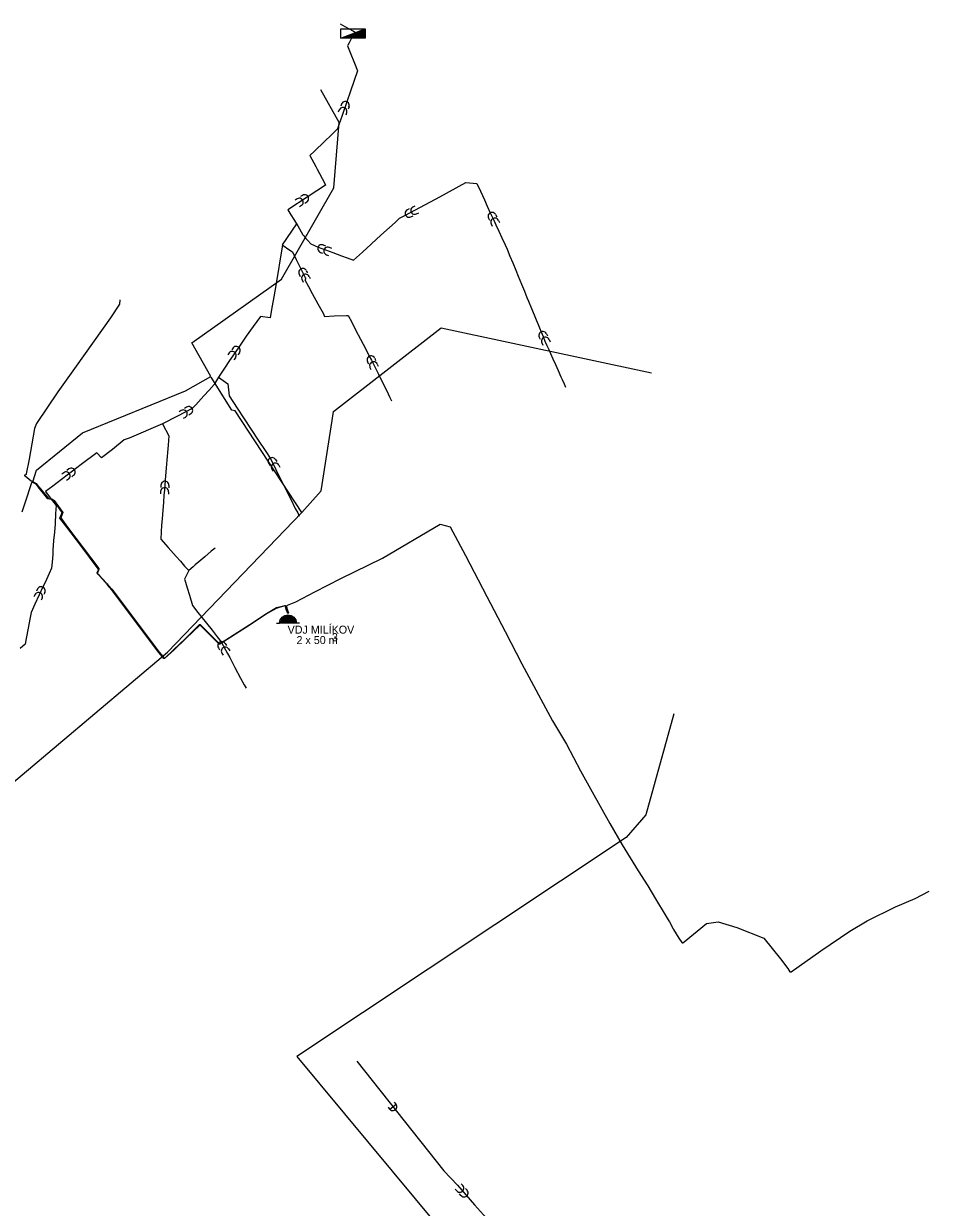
# Model space of a CAD drawing. Extents: x -445050 to -435119, y -1145927 to -1129778.
# Drawn here: x -442201 to -441070, y -1131257 to -1129778 of the extents above; entities that cross this region are included whole.
import ezdxf

# ---------------------------------------------------------------- set-up
doc = ezdxf.new("R2010")
doc.units = 0
for name, color, linetype in [('Vrstva 14', 7, 'Continuous'), ('Vrstva 16', 7, 'Continuous'), ('Vrstva 3', 7, 'Continuous'), ('Vrstva 32', 7, 'Continuous'), ('Vrstva 35', 7, 'Continuous'), ('Vrstva 41', 7, 'Continuous')]:
    doc.layers.add(name, color=color, linetype=linetype)

msp = doc.modelspace()

# ---------------------------------------------------------------- linework, layer by layer
at = {"layer": 'Vrstva 16'}
for p, q in [((-441885.2, -1130527.1), (-441881.2, -1130527.1)), ((-441885.2, -1130527.1), (-441881.2, -1130527.1)), ((-441856.4, -1130527.1), (-441860.3, -1130527.1)), ((-441856.4, -1130527.1), (-441860.3, -1130527.1))]:
    msp.add_line(p, q, dxfattribs=at)
for points in [[(-441881.2, -1130527.1), (-441880.4, -1130523.1), (-441878.1, -1130519.8), (-441874.8, -1130517.5), (-441870.8, -1130516.7), (-441866.8, -1130517.5), (-441863.4, -1130519.8), (-441861.1, -1130523.1), (-441860.3, -1130527.1)], [(-441881.2, -1130527.1), (-441880.4, -1130523.1), (-441878.1, -1130519.8), (-441874.8, -1130517.5), (-441870.8, -1130516.7), (-441866.8, -1130517.5), (-441863.4, -1130519.8), (-441861.1, -1130523.1), (-441860.3, -1130527.1)], [(-441880, -1130526.1), (-441879.5, -1130523.5), (-441877.4, -1130520.5), (-441874.4, -1130518.4), (-441870.8, -1130517.7), (-441867.1, -1130518.4), (-441864.1, -1130520.5), (-441862, -1130523.5), (-441861.5, -1130526.1)], [(-441880, -1130526.1), (-441879.5, -1130523.5), (-441877.4, -1130520.5), (-441874.4, -1130518.4), (-441870.8, -1130517.7), (-441867.1, -1130518.4), (-441864.1, -1130520.5), (-441862, -1130523.5), (-441861.5, -1130526.1)], [(-441878.8, -1130525.1), (-441878.5, -1130523.9), (-441876.7, -1130521.2), (-441874, -1130519.4), (-441870.8, -1130518.7), (-441867.5, -1130519.4), (-441864.8, -1130521.2), (-441863, -1130523.9), (-441862.7, -1130525.1)], [(-441878.8, -1130525.1), (-441878.5, -1130523.9), (-441876.7, -1130521.2), (-441874, -1130519.4), (-441870.8, -1130518.7), (-441867.5, -1130519.4), (-441864.8, -1130521.2), (-441863, -1130523.9), (-441862.7, -1130525.1)], [(-441877.5, -1130524.1), (-441876, -1130521.9), (-441873.6, -1130520.3), (-441870.8, -1130519.7), (-441867.9, -1130520.3), (-441865.5, -1130521.9), (-441864, -1130524.1)], [(-441877.5, -1130524.1), (-441876, -1130521.9), (-441873.6, -1130520.3), (-441870.8, -1130519.7), (-441867.9, -1130520.3), (-441865.5, -1130521.9), (-441864, -1130524.1)], [(-441875.6, -1130523.1), (-441875.3, -1130522.6), (-441873.2, -1130521.3), (-441870.8, -1130520.8), (-441868.3, -1130521.3), (-441866.2, -1130522.6), (-441865.9, -1130523.1)], [(-441875.6, -1130523.1), (-441875.3, -1130522.6), (-441873.2, -1130521.3), (-441870.8, -1130520.8), (-441868.3, -1130521.3), (-441866.2, -1130522.6), (-441865.9, -1130523.1)], [(-441872.5, -1130522.1), (-441870.8, -1130521.8), (-441869, -1130522.1)], [(-441872.5, -1130522.1), (-441870.8, -1130521.8), (-441869, -1130522.1)]]:
    msp.add_lwpolyline(points, close=True, dxfattribs=at)
at = {"layer": 'Vrstva 3'}
for points in [[(-442184.6, -1130336.3), (-442127.1, -1130289.5), (-441998.7, -1130236.9), (-441967.2, -1130219.2), (-441990.9, -1130177.1), (-441878.7, -1130097.6), (-441813.7, -1129983.6), (-441806.9, -1129901.8), (-441829.8, -1129861.2)], [(-442080.7, -1130123.5), (-442081.3, -1130128.7), (-442092.4, -1130146), (-442135.3, -1130206.3), (-442158.3, -1130238.5), (-442184.8, -1130278), (-442187.1, -1130284.2), (-442193.8, -1130322.3), (-442197.6, -1130340.9), (-442197.7, -1130341.4), (-442199.6, -1130342.3), (-442199.8, -1130343.1), (-442199.9, -1130343.4)], [(-442639.4, -1130985.4), (-442636.3, -1130987.9), (-442568.1, -1130946.4), (-442547.5, -1130933.4), (-442527.4, -1130927.1), (-442481.3, -1130902.1), (-442461.8, -1130915.5), (-442444, -1130928.2), (-442432, -1130939.4), (-442338.4, -1130842.5), (-442282, -1130781.8), (-442258.5, -1130763), (-442251.9, -1130757.7), (-442248.4, -1130755), (-442021.4, -1130563.5), (-441853.6, -1130388.9), (-441829.4, -1130362.1), (-441815.6, -1130274.2), (-441814.1, -1130262.8), (-441679.4, -1130158.4), (-441417.1, -1130214.5)], [(-441853.6, -1130388.9), (-441936.6, -1130262.2), (-441940.7, -1130261.3), (-441966.7, -1130220.1)], [(-442199.8, -1130343.1), (-442199.5, -1130343.2), (-442198.8, -1130343.4), (-442191.3, -1130349.5), (-442190.3, -1130350.1), (-442185.2, -1130352.9), (-442182.6, -1130356.3), (-442182, -1130357.1), (-442169.9, -1130371.4), (-442168, -1130372), (-442164.8, -1130372.2), (-442162.6, -1130373.9), (-442152, -1130388.9), (-442154.5, -1130395.9), (-442146.1, -1130407.4), (-442106.9, -1130459.2), (-442106.8, -1130460), (-442108.6, -1130464.5), (-442108.5, -1130465.1), (-442108, -1130465.6), (-442107.1, -1130466.5), (-442106.4, -1130467.3), (-442097.5, -1130477.3), (-442096.6, -1130478.3), (-442095.8, -1130479.2), (-442094.9, -1130480.2), (-442090.5, -1130485), (-442064, -1130520.3), (-442033.2, -1130561.3), (-442025.4, -1130571.1), (-442024.6, -1130570.9), (-442013.6, -1130560.7), (-441999.1, -1130546.7), (-441981.3, -1130528.9), (-441980.3, -1130528.9), (-441956.7, -1130552.6), (-441955.9, -1130552.7), (-441948.4, -1130548.2), (-441918.4, -1130528.8), (-441897.7, -1130515.1), (-441885.1, -1130507.8), (-441874.4, -1130505.2), (-441873.3, -1130506.2), (-441871.9, -1130510.6), (-441870.5, -1130515.1)], [(-442189.3, -1130350.7), (-442184.6, -1130336.3)], [(-441871.2, -1130515.4), (-441872.9, -1130510.1), (-441874.1, -1130506.5), (-441875, -1130505.7), (-441885.5, -1130508.8), (-441897.5, -1130515.8), (-441918.1, -1130529.2), (-441955.8, -1130553.6), (-441956.6, -1130553.5), (-441980, -1130530.2), (-441980.8, -1130529.9), (-441998.4, -1130546.6), (-442013, -1130560.7), (-442024.9, -1130571.5), (-442025.9, -1130571.6), (-442033.5, -1130561.8), (-442090.8, -1130485.5), (-442096, -1130479.5), (-442097.2, -1130478.2), (-442097.6, -1130477.5), (-442098.9, -1130476.2), (-442106.6, -1130467.7), (-442107.1, -1130467.1), (-442107.7, -1130466.4), (-442108.4, -1130465.7), (-442108.9, -1130465), (-442108.9, -1130464.2), (-442107.5, -1130461), (-442107.4, -1130460.1), (-442107.6, -1130459.3), (-442129.4, -1130430.4), (-442146.9, -1130407.4), (-442155.4, -1130396), (-442152.7, -1130389.1), (-442162.9, -1130374.1), (-442164.6, -1130373.1), (-442168.4, -1130372.4), (-442170.5, -1130371.9), (-442182.7, -1130357.1), (-442185.8, -1130353.3), (-442189.4, -1130351.4), (-442189.8, -1130351.4), (-442190.9, -1130352.1), (-442192, -1130354.7), (-442198.6, -1130374.9), (-442202.9, -1130388.5)], [(-441869.6, -1130514.8), (-441870.8, -1130511.3), (-441872.6, -1130505.9), (-441871.4, -1130504.8), (-441861.1, -1130500.6), (-441837.3, -1130488.3), (-441804.7, -1130471.6), (-441752.9, -1130446.2), (-441681, -1130403.7), (-441668.4, -1130407.1), (-441649.3, -1130442.8), (-441622.7, -1130494.1), (-441599.8, -1130537.5), (-441578.8, -1130578.2), (-441540.5, -1130649.1), (-441523.3, -1130678.6), (-441505.6, -1130711.9), (-441491.2, -1130738.1), (-441468.9, -1130777.6), (-441453.6, -1130804), (-441433.6, -1130836.6), (-441421.7, -1130855.4), (-441411.9, -1130871.6), (-441399.9, -1130891.5), (-441396.1, -1130898), (-441394.7, -1130900.4), (-441389.9, -1130908.9), (-441389.4, -1130909.8), (-441383.1, -1130920.6), (-441379.4, -1130926.1), (-441378.8, -1130926.5), (-441378.1, -1130926.5), (-441376.9, -1130925.9), (-441376.3, -1130925.4), (-441348.3, -1130902.6), (-441333.7, -1130900.4), (-441310.6, -1130907.6), (-441277, -1130920.6), (-441256.1, -1130946.4), (-441246.9, -1130958.6), (-441244.2, -1130962.6), (-441243.5, -1130962.9), (-441242.8, -1130962.8), (-441205.5, -1130936.7), (-441169.6, -1130912.1), (-441147.8, -1130899.3), (-441112.3, -1130881.8), (-441087.8, -1130871), (-441070.3, -1130862)], [(-441389.1, -1130640.5), (-441424.2, -1130766.8), (-441448.8, -1130794.9), (-441859.7, -1131068.7), (-441652.5, -1131317.9)]]:
    msp.add_lwpolyline(points, dxfattribs=at)
at = {"layer": 'Vrstva 32'}
for p, q in [((-441806.9, -1129886.2), (-441808, -1129889)), ((-441803.9, -1129878.8), (-441805, -1129881.6)), ((-441797.6, -1129889.9), (-441798.7, -1129892.7)), ((-441794.6, -1129882.5), (-441795.7, -1129885.3)), ((-441852.7, -1129992.9), (-441855.2, -1129994.5)), ((-441859.4, -1129997.2), (-441862, -1129998.9)), ((-441854.1, -1130005.7), (-441856.6, -1130007.3)), ((-441847.3, -1130001.4), (-441849.8, -1130003)), ((-441721.9, -1130010.8), (-441719.2, -1130009.4)), ((-441714.7, -1130007.1), (-441712.1, -1130005.8)), ((-441717.3, -1130019.7), (-441714.6, -1130018.3)), ((-441710.2, -1130016), (-441707.5, -1130014.7)), ((-441620.6, -1130021.2), (-441619.4, -1130023.9)), ((-441611.6, -1130017), (-441610.3, -1130019.7)), ((-441608.2, -1130024.2), (-441606.9, -1130026.9)), ((-441617.2, -1130028.5), (-441616, -1130031.2)), ((-441826.7, -1130054.9), (-441824, -1130056)), ((-441830.4, -1130064.2), (-441827.6, -1130065.3)), ((-441822.9, -1130067.1), (-441820.1, -1130068.2)), ((-441819.3, -1130057.8), (-441816.5, -1130058.9)), ((-441856.9, -1130091.5), (-441855.5, -1130094.1)), ((-441853.3, -1130098.6), (-441851.9, -1130101.3)), ((-441848, -1130087), (-441846.6, -1130089.6)), ((-441844.3, -1130094.1), (-441843, -1130096.8)), ((-441557.3, -1130170), (-441556, -1130172.7)), ((-441548.2, -1130165.7), (-441546.9, -1130168.4)), ((-441544.8, -1130172.9), (-441543.5, -1130175.7)), ((-441939.3, -1130183.4), (-441941.1, -1130185.7)), ((-441553.8, -1130177.2), (-441552.5, -1130179.9)), ((-441944.3, -1130189.6), (-441946.1, -1130192)), ((-441936.5, -1130195.9), (-441938.3, -1130198.2)), ((-441931.5, -1130189.7), (-441933.3, -1130192)), ((-441771.8, -1130200.5), (-441770.5, -1130203.2)), ((-441762.6, -1130196.4), (-441761.4, -1130199.1)), ((-441768.5, -1130207.8), (-441767.3, -1130210.5)), ((-441759.4, -1130203.7), (-441758.1, -1130206.4)), ((-442004.1, -1130261.6), (-442006.7, -1130263.2)), ((-441997.3, -1130257.5), (-441999.8, -1130259)), ((-441998.9, -1130270.2), (-442001.5, -1130271.7)), ((-441992.1, -1130266), (-441994.6, -1130267.6)), ((-442144.5, -1130334.6), (-442146.8, -1130336.4)), ((-441894.9, -1130327.9), (-441893.4, -1130330.5)), ((-441890.9, -1130334.8), (-441889.4, -1130337.4)), ((-441886.3, -1130322.9), (-441884.8, -1130325.5)), ((-441882.3, -1130329.8), (-441880.8, -1130332.4)), ((-442150.8, -1130339.4), (-442153.2, -1130341.2)), ((-442144.8, -1130347.4), (-442147.2, -1130349.2)), ((-442138.4, -1130342.6), (-442140.8, -1130344.4)), ((-442029.8, -1130362.8), (-442029.9, -1130365.8)), ((-442029.5, -1130354.8), (-442029.6, -1130357.8)), ((-442019.8, -1130363.2), (-442020, -1130366.2)), ((-442019.5, -1130355.2), (-442019.6, -1130358.2)), ((-442186.8, -1130491.8), (-442188.1, -1130494.5)), ((-442183.5, -1130484.6), (-442184.7, -1130487.3)), ((-442177.7, -1130496), (-442179, -1130498.7)), ((-442174.4, -1130488.8), (-442175.6, -1130491.5)), ((-441949.3, -1130552.7), (-441947.7, -1130555.2)), ((-441957.7, -1130558.1), (-441956.1, -1130560.6)), ((-441953.3, -1130564.8), (-441951.7, -1130567.4)), ((-441944.9, -1130559.4), (-441943.3, -1130561.9)), ((-441660, -1131236.4), (-441662, -1131234.1)), ((-441652.6, -1131229.7), (-441654.6, -1131227.5)), ((-441647.3, -1131235.7), (-441649.2, -1131233.5)), ((-441654.7, -1131242.4), (-441656.7, -1131240.1))]:
    msp.add_line(p, q, dxfattribs=at)
for points in [[(-441805.6, -1129778.5), (-441799.8, -1129781.8), (-441789.2, -1129787.8), (-441785.9, -1129789.8)], [(-441791.7, -1129796.7), (-441794.5, -1129802.3), (-441796.1, -1129805.4), (-441796.4, -1129806.2), (-441793, -1129814.6), (-441787.8, -1129827.8), (-441783.9, -1129837.2), (-441792.8, -1129862.6), (-441797.4, -1129876), (-441803.3, -1129893.3), (-441807.3, -1129904.9), (-441809.2, -1129909.9), (-441816.5, -1129917.2), (-441825.3, -1129925.5), (-441837.9, -1129937.6), (-441843.6, -1129943.2), (-441836.1, -1129957), (-441834.4, -1129960.2), (-441825.3, -1129977.3), (-441823.8, -1129980.1), (-441845.8, -1129994.5), (-441871, -1130010.9), (-441867.1, -1130017.1), (-441863.4, -1130022.9), (-441858.7, -1130030.8), (-441858.7, -1130030.8), (-441852.1, -1130042.4), (-441851.2, -1130043.4), (-441848.4, -1130046.7), (-441845.9, -1130049.3), (-441842.3, -1130053.4), (-441833.2, -1130057.7), (-441824, -1130061.1), (-441815, -1130064.3), (-441804.2, -1130068.3), (-441797.1, -1130070.9), (-441789.2, -1130073.8), (-441777.9, -1130063.7), (-441772.1, -1130058.4), (-441767.3, -1130054.1), (-441759.7, -1130047.1), (-441751.1, -1130039.3), (-441737.2, -1130026.7), (-441731.5, -1130021.5), (-441724, -1130017.6), (-441681.4, -1129994.6), (-441648.7, -1129977), (-441635.1, -1129978.2), (-441630.7, -1129987.5), (-441625.7, -1129998.5), (-441622, -1130006.3), (-441618.3, -1130014.6), (-441614, -1130023.9), (-441611.2, -1130029.9), (-441607.6, -1130037.8), (-441603.9, -1130045.8), (-441599.8, -1130054.7), (-441597.3, -1130060.2), (-441593.7, -1130068.7), (-441590.2, -1130077.2), (-441586.5, -1130086.3), (-441583.5, -1130093.8), (-441579.2, -1130103.9), (-441575.7, -1130112.6), (-441572.5, -1130120.6), (-441570.5, -1130125.1), (-441566.7, -1130134.4), (-441563.5, -1130142.3), (-441561, -1130148.5), (-441558.6, -1130154.4), (-441556.9, -1130158.3), (-441554.9, -1130163.3), (-441552.4, -1130169.4), (-441550, -1130174.9), (-441547.6, -1130180.3), (-441545.3, -1130185.5), (-441543, -1130190.4), (-441540.1, -1130197.3), (-441537, -1130204.3), (-441533.7, -1130211.6), (-441530.3, -1130219.5), (-441528.7, -1130222.9), (-441526.2, -1130228.5), (-441524.3, -1130232.7)], [(-441860.2, -1130028.3), (-441865.4, -1130036.2), (-441872.6, -1130046.8), (-441877.9, -1130054.6), (-441868.6, -1130061.2), (-441865.2, -1130063.5), (-441860.5, -1130072.9), (-441854.7, -1130084.8), (-441851.3, -1130091.2), (-441849.2, -1130095.6), (-441848.7, -1130096.5), (-441849.7, -1130098.4), (-441845.2, -1130106.6), (-441840.6, -1130115.3), (-441833.4, -1130128.4), (-441827.1, -1130139.9), (-441825.1, -1130144.1), (-441813.1, -1130143.6), (-441797.8, -1130143), (-441795.7, -1130142.8), (-441791.3, -1130151.5), (-441786.4, -1130160.9), (-441780.3, -1130172.5), (-441773.7, -1130185.2), (-441769.3, -1130193.8), (-441766.5, -1130198.8), (-441763.3, -1130205.4), (-441758, -1130216.1), (-441753, -1130226.5), (-441748.4, -1130235.6), (-441745.7, -1130241), (-441743.6, -1130245.5), (-441741.5, -1130249.7)], [(-441877.7, -1130054.6), (-441886.4, -1130108), (-441889.5, -1130124.3), (-441890.9, -1130133), (-441893, -1130145.8), (-441905.3, -1130144.4), (-441914.1, -1130156.6), (-441922.9, -1130169), (-441932.2, -1130182.6), (-441939.6, -1130193.4), (-441943.8, -1130199.3), (-441949.9, -1130208.7), (-441957.4, -1130219.8), (-441945.8, -1130228.3)], [(-441957.4, -1130219.8), (-441960, -1130224.3), (-441962.9, -1130229.1), (-441969.3, -1130236.2), (-441975.9, -1130243.4), (-441985.9, -1130254.5), (-441990.4, -1130259.1)], [(-441945.8, -1130228.3), (-441944.3, -1130243.5), (-441934.3, -1130258.9), (-441916.7, -1130285.2), (-441907.9, -1130298.5), (-441898.3, -1130313), (-441893.1, -1130321.1), (-441888.4, -1130330)], [(-441990.4, -1130259.1), (-442008.6, -1130268.6), (-442027.5, -1130278.3), (-442019.7, -1130293.4), (-442020.5, -1130304.9), (-442021.3, -1130314), (-442021.7, -1130319.2), (-442022.8, -1130333.4), (-442024.2, -1130348.7), (-442024.5, -1130355)], [(-442027.5, -1130278.3), (-442068.9, -1130296), (-442075.3, -1130298.4), (-442089.9, -1130310.2), (-442103.4, -1130320.8), (-442109.5, -1130314.4), (-442128.8, -1130329.2), (-442139.8, -1130337.3), (-442144.6, -1130341.1), (-442153.4, -1130347.8), (-442164.4, -1130356.2), (-442168.9, -1130359.4), (-442173.3, -1130362.8), (-442167.5, -1130370.8), (-442160.3, -1130380.4), (-442161, -1130390.4), (-442161.6, -1130403.1), (-442162.4, -1130413.7), (-442163.3, -1130424.1), (-442164.2, -1130436), (-442164.4, -1130441.4), (-442165.3, -1130451.2), (-442165.8, -1130458.5), (-442168.9, -1130465.2), (-442172.4, -1130472.7), (-442174.1, -1130476.4), (-442176.8, -1130482.1), (-442181.5, -1130492), (-442186.9, -1130503.6), (-442191.5, -1130513.8), (-442193, -1130522.1), (-442195.1, -1130533.6), (-442197.6, -1130546.6), (-442198.8, -1130553.6), (-442205.1, -1130558.8)], [(-441888.5, -1130330), (-441883.4, -1130340.6), (-441876.8, -1130353.7), (-441867.4, -1130372.2), (-441861.7, -1130383.9), (-441858.7, -1130389.6), (-441857, -1130393.6)], [(-442024.5, -1130355), (-442025.1, -1130361), (-442025.7, -1130367.5), (-442026.2, -1130376.5), (-442027, -1130386.3), (-442027.9, -1130397), (-442028.5, -1130405), (-442029, -1130413.3), (-442029.7, -1130422.2), (-442020.4, -1130432.7), (-442010.4, -1130444.1), (-442005, -1130450), (-442000, -1130455.9), (-441994.7, -1130461.6)], [(-441961.8, -1130433.4), (-441966.6, -1130437.5), (-441974.7, -1130444.4), (-441982.1, -1130450.7), (-441986.5, -1130454.4), (-441989.3, -1130456.8), (-441994.7, -1130461.6)], [(-441994.7, -1130461.6), (-441998.4, -1130469), (-442000.1, -1130472.2), (-441998.9, -1130476.1), (-441996.6, -1130483.3), (-441993.9, -1130492.5), (-441990, -1130505.4), (-441983.3, -1130513.8), (-441972.5, -1130527.3), (-441965.6, -1130536.1), (-441959.1, -1130544.2), (-441954.1, -1130550.4), (-441946.2, -1130565.3), (-441943.5, -1130570.2), (-441937, -1130582.7), (-441930, -1130595.8), (-441925.4, -1130604.3), (-441923.2, -1130608.6)], [(-441676.4, -1131211.3), (-441659.3, -1131229.1), (-441638.1, -1131254), (-441619.4, -1131274.6)]]:
    msp.add_lwpolyline(points, dxfattribs=at)
for centre, start, end in [((-441799.3, -1129880.6), 338.2077, 158.2088), ((-441802.2, -1129888.1), 338.2077, 158.2088), ((-441850, -1129997.1), 302.5841, 122.5852), ((-441856.7, -1130001.5), 302.5841, 122.5852), ((-441712.5, -1130011.6), 117.2982, 297.2993), ((-441719.6, -1130015.3), 117.2982, 297.2993), ((-441616.1, -1130019.1), 25.1744, 205.1755), ((-441612.7, -1130026.3), 25.1744, 205.1755), ((-441828.6, -1130059.5), 68.6864, 248.6875), ((-441821.1, -1130062.5), 68.6864, 248.6875), ((-441852.4, -1130089.2), 26.8318, 206.8329), ((-441848.8, -1130096.4), 26.8318, 206.8329), ((-441552.7, -1130167.9), 25.313, 205.3141), ((-441549.3, -1130175.1), 25.313, 205.3141), ((-441940.4, -1130192.8), 321.2503, 141.2514), ((-441935.4, -1130186.5), 321.2503, 141.2514), ((-441767.2, -1130198.4), 24.2027, 204.2038), ((-441763.9, -1130205.7), 24.2027, 204.2038), ((-442001.5, -1130265.9), 301.3083, 121.3093), ((-441994.7, -1130261.7), 301.3083, 121.3093), ((-441890.6, -1130325.4), 30.1484, 210.1495), ((-442141.4, -1130338.6), 306.8961, 126.8972), ((-441886.6, -1130332.3), 30.1484, 210.1495), ((-442147.8, -1130343.4), 306.8961, 126.8972), ((-442024.5, -1130355), 357.5568, 177.5579), ((-442024.8, -1130363), 357.5568, 177.5579), ((-442178.9, -1130486.7), 335.1178, 155.1188), ((-442182.3, -1130493.9), 335.1178, 155.1188), ((-441953.5, -1130555.4), 32.8593, 212.8604), ((-441949.1, -1130562.1), 32.8593, 212.8604), ((-441656.3, -1131233.1), 221.6612, 41.6623), ((-441651, -1131239), 221.6612, 41.6623)]:
    msp.add_arc(centre, 5, start, end, dxfattribs=at)
at = {"layer": 'Vrstva 35'}
for p, q in [((-441743.7, -1131134.3), (-441745.5, -1131131.9)), ((-441743.7, -1131134.3), (-441735.8, -1131128.1)), ((-441735.8, -1131128.1), (-441737.7, -1131125.7))]:
    msp.add_line(p, q, dxfattribs=at)
msp.add_lwpolyline([(-441784.7, -1131074.4), (-441676.4, -1131211.3)], dxfattribs=at)
msp.add_arc((-441739.8, -1131131.2), 5, 218.3511, 38.3518, dxfattribs=at)
at = {"layer": 'Vrstva 41'}
msp.add_lwpolyline([(-441804.8, -1129796.7), (-441804.8, -1129784.7), (-441774.4, -1129784.7)], dxfattribs=at)
for points in [[(-441774.4, -1129784.7), (-441774.4, -1129796.7), (-441804.8, -1129796.7)], [(-441775.2, -1129785.9), (-441775.2, -1129795.9), (-441800.6, -1129795.9)], [(-441776, -1129787.1), (-441776, -1129795.1), (-441796.4, -1129795.1)], [(-441776.8, -1129788.2), (-441776.8, -1129794.3), (-441792.2, -1129794.3)], [(-441777.6, -1129789.4), (-441777.6, -1129793.5), (-441788, -1129793.5)], [(-441778.4, -1129790.6), (-441778.4, -1129792.7), (-441783.8, -1129792.7)]]:
    msp.add_lwpolyline(points, close=True, dxfattribs=at)

# ---------------------------------------------------------------- texts
at = {"layer": 'Vrstva 14'}
msp.add_text('3', height=10, dxfattribs=at).set_placement((-441816, -1130549.8))
at = {"layer": 'Vrstva 16'}
for s, p in [('VDJ MILÍKOV ', (-441871.3, -1130540.4)), ('   2 x 50 m', (-441871.3, -1130553.4))]:
    msp.add_text(s, height=10, dxfattribs=at).set_placement(p)

doc.saveas('drawing.dxf')
